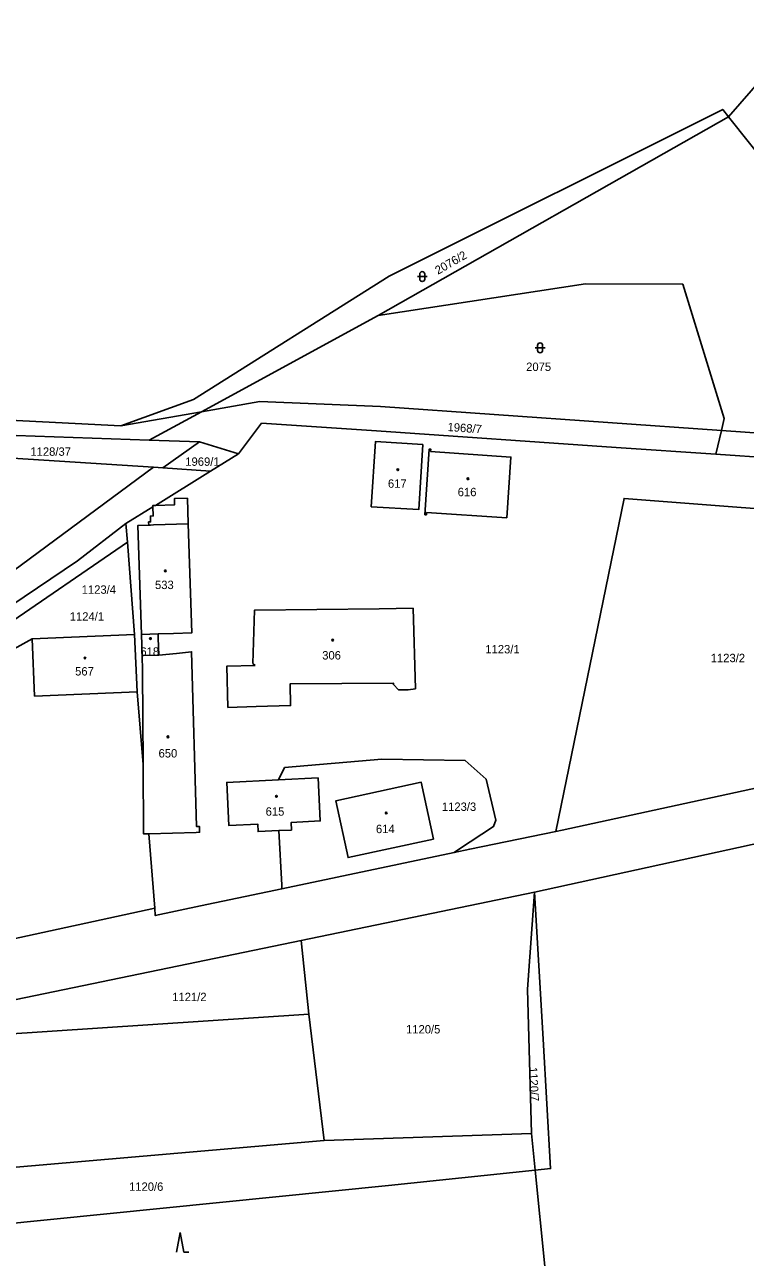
# Model space of a CAD drawing. Extents: x -794765 to -785424, y -1118958 to -1108731.
# Drawn here: x -786815.6 to -786669.6, y -1115772 to -1115522.2 of the extents above; entities that cross this region are included whole.
import ezdxf

# ---------------------------------------------------------------- set-up
doc = ezdxf.new("R2010")
doc.units = 0
for name, color, linetype in [('Level 66', 7, 'Continuous'), ('Level 75', 7, 'Continuous'), ('Level 76', 7, 'Continuous'), ('Level 77', 7, 'Continuous'), ('Level 79', 7, 'Continuous')]:
    doc.layers.add(name, color=color, linetype=linetype)

msp = doc.modelspace()

# ---------------------------------------------------------------- linework, layer by layer
at = {"layer": 'Level 66'}
for p, q in [((-786736.04, -1115573.28), (-786734.04, -1115573.28)), ((-786735.54, -1115572.78), (-786735.54, -1115573.78)), ((-786734.54, -1115573.78), (-786734.54, -1115572.78)), ((-786712.18, -1115587.72), (-786710.18, -1115587.72)), ((-786711.68, -1115587.22), (-786711.68, -1115588.22)), ((-786710.68, -1115588.22), (-786710.68, -1115587.22)), ((-786784.09, -1115766.92), (-786784.84, -1115770.92)), ((-786783.34, -1115770.92), (-786784.09, -1115766.92)), ((-786783.34, -1115770.92), (-786782.34, -1115770.92))]:
    msp.add_line(p, q, dxfattribs=at)
for centre, start, end in [((-786735.04, -1115572.78), 0, 180), ((-786735.04, -1115573.78), 180, 359.9879), ((-786711.18, -1115587.22), 0, 180), ((-786711.18, -1115588.22), 180, 359.9879)]:
    msp.add_arc(centre, 0.5, start, end, dxfattribs=at)
at = {"layer": 'Level 75'}
for p, q in [((-786672.98, -1115540.91), (-786743.97, -1115581.14)), ((-786743.97, -1115581.14), (-786779.79, -1115600.67)), ((-786921.27, -1115597.08), (-786796.1, -1115603.54)), ((-786796.1, -1115603.54), (-786779.79, -1115600.67)), ((-786779.79, -1115600.67), (-786790.33, -1115606.42)), ((-786789.48, -1115611.9), (-786933.2, -1115602.56)), ((-786674.46, -1115604.45), (-786673.88, -1115602.02)), ((-786790.33, -1115606.42), (-786837.35, -1115604.8)), ((-786675.61, -1115609.26), (-786674.46, -1115604.45)), ((-786644.31, -1115606.56), (-786674.46, -1115604.45)), ((-786790.33, -1115606.42), (-786780.17, -1115606.77)), ((-786780.17, -1115606.77), (-786787.6, -1115612)), ((-786772.25, -1115609.2), (-786780.17, -1115606.77)), ((-786777.94, -1115612.72), (-786772.25, -1115609.2)), ((-786644.99, -1115611.37), (-786675.61, -1115609.26)), ((-786787.6, -1115612), (-786789.48, -1115611.9)), ((-786789.1, -1115619.62), (-786777.94, -1115612.72)), ((-786787.6, -1115612), (-786777.94, -1115612.72)), ((-786795.06, -1115623.32), (-786789.6, -1115619.93)), ((-786794.77, -1115627.05), (-786795.06, -1115623.32)), ((-786793.3, -1115645.76), (-786794.77, -1115627.05)), ((-786736.88, -1115640.48), (-786743.76, -1115640.56)), ((-786791.94, -1115645.77), (-786788.54, -1115645.66)), ((-786788.54, -1115645.66), (-786785.4, -1115645.58)), ((-786851.55, -1115667.72), (-786814.08, -1115646.63)), ((-786814.08, -1115646.63), (-786793.3, -1115645.76)), ((-786792.79, -1115657.4), (-786793.3, -1115645.76)), ((-786791.94, -1115645.77), (-786791.81, -1115650.07)), ((-786791.58, -1115672.15), (-786792.79, -1115657.4)), ((-786524.97, -1115657.02), (-786712.31, -1115697.97)), ((-786789.2, -1115701.2), (-786790.43, -1115686.15)), ((-786763.48, -1115697.3), (-786728.61, -1115689.93)), ((-786779.93, -1115700.77), (-786763.48, -1115697.3)), ((-786712.31, -1115697.97), (-786759.56, -1115707.76)), ((-786895.26, -1115724.29), (-786789.2, -1115701.2)), ((-786759.56, -1115707.76), (-786866.69, -1115729.95)), ((-786759.56, -1115707.76), (-786757.99, -1115722.68)), ((-786757.99, -1115722.68), (-786866.69, -1115729.95)), ((-786754.91, -1115748.31), (-786757.99, -1115722.68)), ((-786754.91, -1115748.31), (-786712.9, -1115746.86)), ((-786712.15, -1115754.3), (-786712.9, -1115746.86)), ((-786879.23, -1115759.05), (-786754.91, -1115748.31)), ((-786710.19, -1115773.76), (-786712.15, -1115754.3))]:
    msp.add_line(p, q, dxfattribs=at)
for points in [[(-786518.64, -1115629.72), (-786517.96, -1115586.56), (-786552.12, -1115542.07), (-786585.86, -1115514.62), (-786569.74, -1115484.56), (-786599.09, -1115456.01), (-786672.98, -1115540.91)], [(-786796.1, -1115603.54), (-786781.38, -1115598.17), (-786741.73, -1115573.22), (-786674.19, -1115539.4), (-786672.98, -1115540.91)], [(-786672.98, -1115540.91), (-786646.94, -1115573.57), (-786644.31, -1115606.56)], [(-786673.88, -1115602.02), (-786682.27, -1115574.84), (-786702.01, -1115574.78), (-786743.97, -1115581.14)], [(-786779.79, -1115600.67), (-786767.96, -1115598.59), (-786743.47, -1115599.61), (-786674.46, -1115604.45)], [(-786675.61, -1115609.26), (-786695.74, -1115607.88), (-786744.3, -1115604.54), (-786767.59, -1115602.98), (-786772.25, -1115609.2)], [(-786734.93, -1115607.32), (-786744.54, -1115606.72), (-786745.37, -1115619.89), (-786735.77, -1115620.49), (-786734.93, -1115607.32)], [(-786717.91, -1115622.14), (-786717.1, -1115609.83), (-786733.37, -1115608.68), (-786733.34, -1115608.23), (-786733.64, -1115608.21), (-786734.5, -1115621.52), (-786734.2, -1115621.54), (-786734.17, -1115621.09), (-786717.91, -1115622.14)], [(-786789.48, -1115611.9), (-786858.06, -1115662.6), (-786861.87, -1115666.81)], [(-786782.62, -1115618.16), (-786785.26, -1115618.24), (-786785.23, -1115619.52), (-786789.1, -1115619.62)], [(-786785.4, -1115645.58), (-786781.75, -1115645.47), (-786782.45, -1115623.38), (-786782.62, -1115618.16)], [(-786707.98, -1115685.68), (-786694.16, -1115618.2), (-786645.78, -1115621.97)], [(-786789.6, -1115619.93), (-786789.55, -1115621.77), (-786790.1, -1115621.79), (-786790.07, -1115622.93), (-786790.08, -1115622.97), (-786790.48, -1115622.98), (-786790.46, -1115623.62)], [(-786789.6, -1115619.93), (-786789.61, -1115619.64), (-786789.1, -1115619.62)], [(-786795.06, -1115623.32), (-786804.85, -1115630.88), (-786848.57, -1115660.33), (-786867.17, -1115676.51)], [(-786790.46, -1115623.62), (-786792.64, -1115623.68), (-786791.94, -1115645.77)], [(-786794.77, -1115627.05), (-786846.02, -1115662.21), (-786851.55, -1115667.72)], [(-786774.42, -1115660.54), (-786768.67, -1115660.37), (-786761.72, -1115660.17), (-786761.78, -1115655.77), (-786740.88, -1115655.62), (-786740.89, -1115655.94), (-786739.83, -1115656.98), (-786737.91, -1115657), (-786736.44, -1115656.77), (-786736.88, -1115640.48)], [(-786743.76, -1115640.56), (-786769, -1115640.83), (-786769.39, -1115651.64), (-786768.88, -1115652.08)], [(-786788.41, -1115649.96), (-786788.52, -1115646.51), (-786788.54, -1115645.66)], [(-786792.79, -1115657.4), (-786813.58, -1115658.27), (-786814.08, -1115646.63)], [(-786791.81, -1115650.07), (-786791.5, -1115650.06), (-786788.41, -1115649.96)], [(-786791.81, -1115650.07), (-786791.71, -1115653.16), (-786791.58, -1115672.15)], [(-786790.43, -1115686.15), (-786780.83, -1115685.87), (-786780.16, -1115685.85), (-786780.18, -1115684.65), (-786780.75, -1115684.68), (-786781.76, -1115649.29), (-786784.8, -1115649.6), (-786788.41, -1115649.96)], [(-786768.88, -1115652.08), (-786774.66, -1115652.21), (-786774.42, -1115660.54)], [(-786790.43, -1115686.15), (-786791.49, -1115686.18), (-786791.58, -1115672.15)], [(-786764.15, -1115675.22), (-786762.94, -1115672.74), (-786743.26, -1115671.01), (-786726.36, -1115671.31), (-786722.13, -1115675.09), (-786720.13, -1115683.39), (-786720.61, -1115684.68), (-786727.72, -1115689.35), (-786728.61, -1115689.93)], [(-786707.98, -1115685.68), (-786706.73, -1115685.42), (-786648.28, -1115672.74)], [(-786764.15, -1115675.22), (-786774.63, -1115675.75), (-786774.19, -1115684.48), (-786768.37, -1115684.19), (-786768.3, -1115685.71), (-786764.07, -1115685.51)], [(-786764.07, -1115685.51), (-786761.54, -1115685.39), (-786761.59, -1115683.85), (-786755.72, -1115683.55), (-786756.16, -1115674.82), (-786764.15, -1115675.22)], [(-786732.75, -1115687.21), (-786735.24, -1115675.71), (-786752.56, -1115679.48), (-786750.08, -1115690.96), (-786732.75, -1115687.21)], [(-786763.48, -1115697.3), (-786763.52, -1115696.56), (-786764.07, -1115685.51)], [(-786728.61, -1115689.93), (-786725.43, -1115689.26), (-786707.98, -1115685.68)], [(-786712.9, -1115746.86), (-786713.71, -1115717.6), (-786712.31, -1115697.97)], [(-786712.31, -1115697.97), (-786710.52, -1115727.74), (-786709.06, -1115753.98), (-786712.15, -1115754.3)], [(-786789.2, -1115701.2), (-786789.12, -1115702.71), (-786779.93, -1115700.77)], [(-786712.15, -1115754.3), (-786741.91, -1115757.42), (-786821.8, -1115765.46), (-786867.05, -1115769.85), (-786875.79, -1115765.76)]]:
    msp.add_lwpolyline(points, dxfattribs=at)
at = {"layer": 'Level 77'}
for p, q in [((-786790.46, -1115623.62), (-786790.06, -1115623.61)), ((-786790.06, -1115623.61), (-786789.5, -1115623.59)), ((-786789.5, -1115623.59), (-786782.45, -1115623.38))]:
    msp.add_line(p, q, dxfattribs=at)
at = {"layer": 'Level 79'}
for centre in [(-786739.99, -1115612.4), (-786725.79, -1115614.23), (-786787.09, -1115632.9), (-786790.1, -1115646.6), (-786753.2, -1115646.91), (-786803.35, -1115650.55), (-786786.56, -1115666.51), (-786764.58, -1115678.56), (-786742.34, -1115681.94)]:
    msp.add_circle(centre, 0.175, dxfattribs=at)

# ---------------------------------------------------------------- texts
at = {"layer": 'Level 76'}
for s, rotation, p in [('2076/2', 30, (-786731.85, -1115572.92)), ('1968/7', 356, (-786729.97, -1115604.56)), ('1120/7', 273, (-786713.46, -1115733.45))]:
    msp.add_text(s, height=1.7, rotation=rotation, dxfattribs=at).set_placement(p)
for s, p in [('2075', (-786714, -1115592.4)), ('1128/37', (-786814.42, -1115609.58)), ('1969/1', (-786783.04, -1115611.61)), ('617', (-786742, -1115616.06)), ('616', (-786727.86, -1115617.77)), ('1123/4', (-786804.03, -1115637.53)), ('533', (-786789.18, -1115636.58)), ('1124/1', (-786806.45, -1115642.98)), ('1123/1', (-786722.27, -1115649.61)), ('618', (-786792.14, -1115650.09)), ('306', (-786755.31, -1115650.85)), ('1123/2', (-786676.61, -1115651.39)), ('567', (-786805.36, -1115654.09)), ('650', (-786788.46, -1115670.7)), ('1123/3', (-786731.07, -1115681.52)), ('615', (-786766.77, -1115682.49)), ('614', (-786744.43, -1115686.02)), ('1121/2', (-786785.69, -1115720.05)), ('1120/5', (-786738.33, -1115726.6)), ('1120/6', (-786794.44, -1115758.48))]:
    msp.add_text(s, height=1.7, dxfattribs=at).set_placement(p)

doc.saveas('drawing.dxf')
